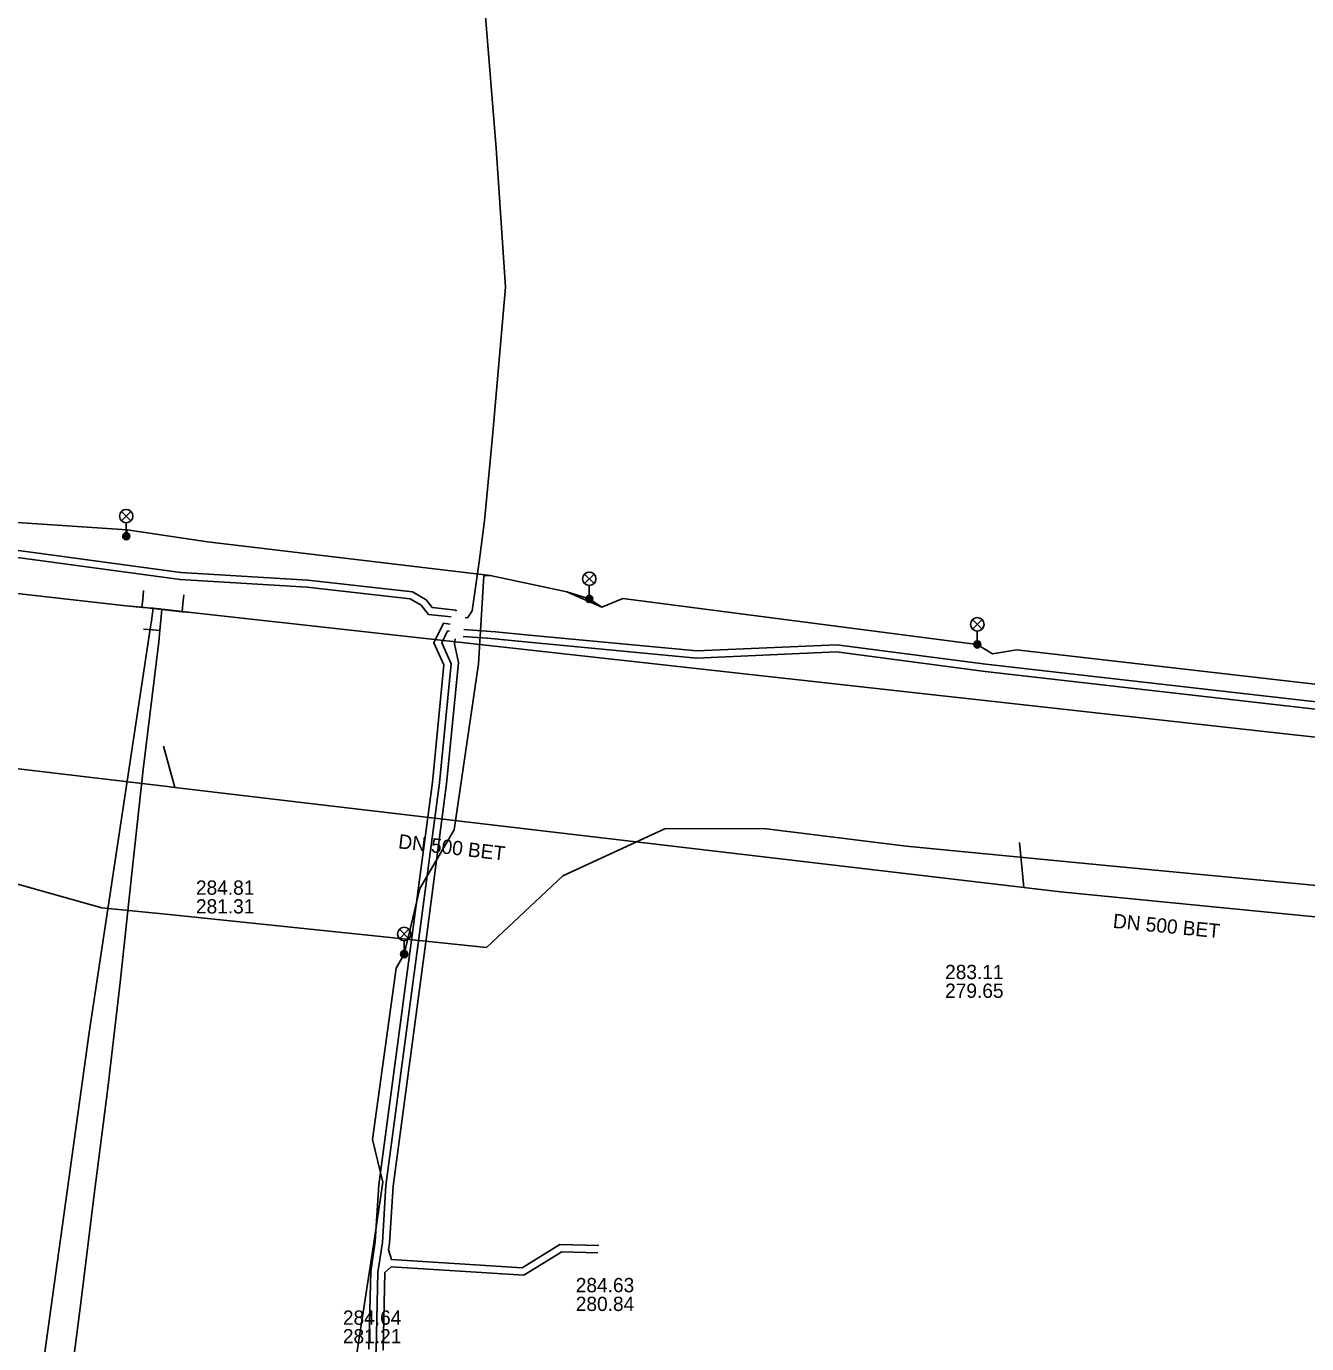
# Model space of a CAD drawing. Extents: x -595540 to -593988, y -1160850 to -1159202.
# Drawn here: x -594220.6 to -594148.9, y -1160478.9 to -1160405.2 of the extents above; entities that cross this region are included whole.
import ezdxf

# ---------------------------------------------------------------- set-up
doc = ezdxf.new("R2010")
doc.units = 0
for name, color, linetype in [('BVK-DESTOVA_popisy', 7, 'Continuous'), ('BVK-DESTOVA_trasa sítě', 7, 'Continuous'), ('BVK-VODOVOD_trasa neprovozované sítě', 7, 'Continuous'), ('BVK-VODOVOD_trasa sítě', 7, 'Continuous'), ('BVK-VODOVOD_trasa zrušené sítě', 7, 'Continuous'), ('CETIN_kabel podzemní', 7, 'Continuous'), ('DESTOVA-NEPROVOZOVANA_popisy', 7, 'Continuous'), ('DESTOVA_trasa neprovozované sítě', 7, 'Continuous'), ('EON-NN_kabel', 7, 'Continuous'), ('SPLASKOVA_popisy neprovozované sítě', 7, 'Continuous'), ('TSB_kabel VO', 7, 'Continuous'), ('TSB_lampy VO', 7, 'Continuous')]:
    doc.layers.add(name, color=color, linetype=linetype)

msp = doc.modelspace()

# ---------------------------------------------------------------- linework, layer by layer
at = {"layer": 'BVK-DESTOVA_popisy'}
for p, q in [((-594211.057, -1160453.94), (-594211.057, -1160453.94)), ((-594169.103, -1160458.665), (-594169.103, -1160458.665))]:
    msp.add_line(p, q, dxfattribs=at)
at = {"layer": 'BVK-DESTOVA_trasa sítě'}
for points in [[(-594244.324, -1160444), (-594212.646, -1160447.758), (-594212.249, -1160447.805), (-594203.869, -1160448.799)], [(-594203.869, -1160448.799), (-594165.305, -1160453.34), (-594164.69, -1160453.413), (-594162.641, -1160453.654)], [(-594162.641, -1160453.654), (-594123.847, -1160457.456), (-594121.411, -1160457.695)]]:
    msp.add_lwpolyline(points, dxfattribs=at)
at = {"layer": 'BVK-VODOVOD_trasa neprovozované sítě'}
for p, q in [((-594212.97, -1160437.84), (-594213.62, -1160437.77)), ((-594212.97, -1160437.84), (-594213.02, -1160438.44)), ((-594212.31, -1160437.92), (-594212.97, -1160437.84))]:
    msp.add_line(p, q, dxfattribs=at)
for points in [[(-594213.62, -1160437.77), (-594214.09, -1160437.72), (-594214.96, -1160437.63)], [(-594211.32, -1160438.02), (-594211.83, -1160437.97), (-594212.31, -1160437.92)], [(-594213.02, -1160438.44), (-594213.08, -1160439.02), (-594213.14, -1160439.66), (-594214.01, -1160446.81), (-594214.67, -1160452.79), (-594215.3, -1160458.72), (-594216, -1160464.65), (-594216.76, -1160470.59), (-594217.49, -1160476.51), (-594218.25, -1160482.46)]]:
    msp.add_lwpolyline(points, dxfattribs=at)
at = {"layer": 'BVK-VODOVOD_trasa sítě'}
for points in [[(-594214.96, -1160437.63), (-594274.08, -1160430.95), (-594306.27, -1160427.23), (-594312.47, -1160426.57), (-594313.618, -1160426.436), (-594314.569, -1160426.328)], [(-594214.09, -1160437.72), (-594214.04, -1160437.29), (-594213.99, -1160436.78)], [(-594211.83, -1160437.97), (-594211.79, -1160437.53), (-594211.74, -1160437.02)], [(-594113.276, -1160448.503), (-594125.48, -1160447.53), (-594211.32, -1160438.02)], [(-594213.08, -1160439.02), (-594213.49, -1160438.98), (-594214, -1160438.94)]]:
    msp.add_lwpolyline(points, dxfattribs=at)
at = {"layer": 'BVK-VODOVOD_trasa zrušené sítě'}
for p, q in [((-594214.027, -1160437.733), (-594214.96, -1160437.63)), ((-594213.459, -1160437.778), (-594214.027, -1160437.733)), ((-594213.459, -1160437.778), (-594213.551, -1160438.474)), ((-594211.32, -1160438.02), (-594213.459, -1160437.778))]:
    msp.add_line(p, q, dxfattribs=at)
msp.add_lwpolyline([(-594213.551, -1160438.474), (-594213.601, -1160438.814), (-594217.04, -1160461.53), (-594223.63, -1160508.9), (-594224.89, -1160519.02), (-594236.25, -1160529.2), (-594237.67, -1160530.464), (-594245.437, -1160537.304), (-594246.41, -1160538.23), (-594259.22, -1160548.81), (-594259.91, -1160549.45), (-594262.55, -1160548.76), (-594263.54, -1160549.66), (-594264.87, -1160550.76), (-594266.65, -1160552.25), (-594269.22, -1160554.37), (-594269.44, -1160560.5), (-594269.912, -1160561.147), (-594270.246, -1160561.625)], dxfattribs=at)
at = {"layer": 'CETIN_kabel podzemní'}
msp.add_lwpolyline([(-594222.52, -1160452.81), (-594216.33, -1160454.54), (-594212.55, -1160454.93), (-594194.78, -1160456.76), (-594190.51, -1160452.76), (-594184.77, -1160450.1), (-594179.1, -1160450.13), (-594171.29, -1160451.1), (-594162.22, -1160451.97), (-594159.7, -1160452.21), (-594139.662, -1160454.119)], dxfattribs=at)
at = {"layer": 'DESTOVA-NEPROVOZOVANA_popisy'}
msp.add_line((-594189.786, -1160477.121), (-594189.786, -1160477.121), dxfattribs=at)
at = {"layer": 'DESTOVA_trasa neprovozované sítě'}
for p, q in [((-594212.873, -1160445.498), (-594212.249, -1160447.805)), ((-594164.93, -1160450.883), (-594164.69, -1160453.413))]:
    msp.add_line(p, q, dxfattribs=at)
at = {"layer": 'EON-NN_kabel'}
for points in [[(-594194.904, -1160403.956), (-594194.236, -1160412.008), (-594193.719, -1160419.801), (-594194.444, -1160428.15), (-594194.905, -1160432.885), (-594195.196, -1160435.178), (-594195.581, -1160437.924), (-594195.824, -1160438.297), (-594195.973, -1160438.308)], [(-594196.463, -1160437.929), (-594196.507, -1160437.886), (-594197.826, -1160437.737), (-594198.169, -1160437.3), (-594198.935, -1160436.856), (-594204.795, -1160436.195), (-594211.899, -1160435.767), (-594220.3, -1160434.636), (-594226.529, -1160433.819), (-594235.45, -1160432.714), (-594247.97, -1160431.519), (-594257.366, -1160430.496), (-594266.358, -1160429.88), (-594275.304, -1160428.268), (-594276.054, -1160427.775), (-594276.181, -1160427.178), (-594276.328, -1160424.743), (-594276.747, -1160421.438), (-594277.287, -1160420.257), (-594279.851, -1160420.114), (-594280.216, -1160420.099), (-594286.508, -1160419.735), (-594287.944, -1160419.605)], [(-594196.773, -1160438.259), (-594198.037, -1160438.116), (-594198.437, -1160437.608), (-594199.063, -1160437.244), (-594204.829, -1160436.593), (-594211.937, -1160436.165), (-594220.352, -1160435.032), (-594226.579, -1160434.215), (-594235.494, -1160433.112), (-594248.01, -1160431.917), (-594257.402, -1160430.894), (-594266.408, -1160430.278), (-594275.456, -1160428.648), (-594276.412, -1160428.019), (-594276.579, -1160427.232), (-594276.726, -1160424.781), (-594277.137, -1160421.548), (-594277.551, -1160420.643), (-594279.84, -1160420.515), (-594280.236, -1160420.499), (-594286.547, -1160420.133), (-594287.98, -1160420.005)], [(-594201.372, -1160479.267), (-594201.269, -1160474.903), (-594201.013, -1160473.236), (-594200.817, -1160470.049), (-594198.927, -1160455.934), (-594197.817, -1160447.512), (-594197.171, -1160440.946), (-594197.739, -1160439.705), (-594197.202, -1160438.614), (-594196.819, -1160438.657)], [(-594169.531, -1160502.245), (-594173.494, -1160503.747), (-594180.8, -1160503.48), (-594187.546, -1160503.094), (-594187.889, -1160502.856), (-594188.148, -1160502.677), (-594187.802, -1160492.632), (-594187.662, -1160491.907), (-594188.169, -1160491.592), (-594194.774, -1160490.25), (-594201.117, -1160488.96), (-594201.746, -1160488.398), (-594201.892, -1160487.481), (-594200.973, -1160479.294), (-594200.87, -1160474.938), (-594200.615, -1160473.279), (-594200.419, -1160470.088), (-594198.53, -1160455.987), (-594197.42, -1160447.558), (-594196.762, -1160440.878), (-594197.296, -1160439.711), (-594196.968, -1160439.042), (-594196.864, -1160439.053)], [(-594188.504, -1160473.456), (-594190.68, -1160473.404), (-594192.792, -1160474.699), (-594200.098, -1160474.239), (-594200.273, -1160473.688), (-594200.217, -1160473.322), (-594200.021, -1160470.127), (-594198.133, -1160456.04), (-594197.023, -1160447.604), (-594196.353, -1160440.81), (-594196.573, -1160439.775), (-594196.543, -1160439.48)], [(-594196.094, -1160439.359), (-594194.77, -1160439.455), (-594194.726, -1160439.457), (-594192.627, -1160439.655), (-594183.025, -1160440.562), (-594175.18, -1160440.223), (-594166.868, -1160441.308), (-594148.038, -1160443.456), (-594139.714, -1160444.195), (-594132.759, -1160445.13), (-594123.636, -1160446.031), (-594123.002, -1160445.543), (-594122.98, -1160445.265), (-594122.605, -1160445.028), (-594122.518, -1160445.033)], [(-594122.014, -1160444.877), (-594122.247, -1160444.453), (-594122.426, -1160444.442), (-594123.364, -1160445.034), (-594123.387, -1160445.334), (-594123.753, -1160445.616), (-594132.713, -1160444.732), (-594139.67, -1160443.797), (-594147.998, -1160443.058), (-594166.82, -1160440.91), (-594175.162, -1160439.821), (-594183.015, -1160440.162), (-594192.589, -1160439.257), (-594194.288, -1160439.097), (-594196.048, -1160438.959)], [(-594188.553, -1160473.855), (-594190.572, -1160473.806), (-594192.69, -1160475.107), (-594200.122, -1160474.639), (-594200.471, -1160474.962), (-594200.574, -1160479.321)]]:
    msp.add_lwpolyline(points, dxfattribs=at)
at = {"layer": 'SPLASKOVA_popisy neprovozované sítě'}
msp.add_line((-594202.827, -1160477.092), (-594202.827, -1160477.092), dxfattribs=at)
at = {"layer": 'TSB_kabel VO'}
for points in [[(-594115.77, -1160439.63), (-594116.44, -1160439.53), (-594117.23, -1160445.35), (-594120.12, -1160445.03), (-594139.21, -1160442.73), (-594140.42, -1160443.22), (-594141.24, -1160442.85), (-594165.1, -1160440.11), (-594166.45, -1160440.32), (-594167.3, -1160439.8), (-594187.15, -1160437.23), (-594188.32, -1160437.71), (-594189.03, -1160437.25), (-594190.28, -1160436.85), (-594194.58, -1160435.94), (-594210.41, -1160434.05), (-594214.9, -1160433.39), (-594214.96, -1160433.74), (-594214.9, -1160433.39), (-594222.48, -1160432.88)], [(-594202.055, -1160479.49), (-594201.123, -1160473.426), (-594200.59, -1160469.909), (-594201.172, -1160467.513), (-594199.842, -1160457.928), (-594199.396, -1160457.139), (-594198.516, -1160453.462), (-594196.596, -1160450.188), (-594195.23, -1160440.889), (-594194.928, -1160435.962), (-594194.58, -1160435.94), (-594190.28, -1160436.85), (-594188.32, -1160437.71), (-594187.15, -1160437.23), (-594167.3, -1160439.8), (-594166.45, -1160440.32), (-594165.1, -1160440.11), (-594141.24, -1160442.85), (-594140.42, -1160443.22), (-594139.21, -1160442.73), (-594120.12, -1160445.03), (-594117.23, -1160445.35), (-594116.44, -1160439.53), (-594115.77, -1160439.63)]]:
    msp.add_lwpolyline(points, dxfattribs=at)
at = {"layer": 'TSB_lampy VO'}
for p, q in [((-594215.225, -1160432.88), (-594214.695, -1160432.35)), ((-594215.225, -1160432.35), (-594214.695, -1160432.88)), ((-594215.225, -1160432.88), (-594214.695, -1160432.35)), ((-594215.225, -1160432.35), (-594214.695, -1160432.88)), ((-594214.96, -1160432.99), (-594214.96, -1160433.74)), ((-594214.96, -1160432.99), (-594214.96, -1160433.74)), ((-594189.295, -1160436.39), (-594188.765, -1160435.86)), ((-594189.295, -1160435.86), (-594188.765, -1160436.39)), ((-594189.295, -1160436.39), (-594188.765, -1160435.86)), ((-594189.295, -1160435.86), (-594188.765, -1160436.39)), ((-594189.03, -1160436.5), (-594189.03, -1160437.25)), ((-594189.03, -1160436.5), (-594189.03, -1160437.25)), ((-594167.565, -1160438.94), (-594167.035, -1160438.41)), ((-594167.565, -1160438.41), (-594167.035, -1160438.94)), ((-594167.565, -1160438.94), (-594167.035, -1160438.41)), ((-594167.565, -1160438.41), (-594167.035, -1160438.94)), ((-594167.3, -1160439.05), (-594167.3, -1160439.8)), ((-594167.3, -1160439.05), (-594167.3, -1160439.8)), ((-594199.661, -1160456.279), (-594199.131, -1160455.749)), ((-594199.661, -1160455.749), (-594199.131, -1160456.279)), ((-594199.661, -1160456.279), (-594199.131, -1160455.749)), ((-594199.661, -1160455.749), (-594199.131, -1160456.279)), ((-594199.396, -1160456.389), (-594199.396, -1160457.139)), ((-594199.396, -1160456.389), (-594199.396, -1160457.139))]:
    msp.add_line(p, q, dxfattribs=at)
for centre, radius in [((-594214.96, -1160432.615), 0.375), ((-594214.96, -1160432.615), 0.375), ((-594214.96, -1160433.74), 0.2), ((-594214.96, -1160433.74), 0.2), ((-594214.96, -1160433.74), 0.145), ((-594214.96, -1160433.74), 0.145), ((-594214.96, -1160433.74), 0.0876), ((-594214.96, -1160433.74), 0.0876), ((-594189.03, -1160436.125), 0.375), ((-594189.03, -1160436.125), 0.375), ((-594189.03, -1160437.25), 0.2), ((-594189.03, -1160437.25), 0.2), ((-594189.03, -1160437.25), 0.145), ((-594189.03, -1160437.25), 0.145), ((-594189.03, -1160437.25), 0.0876), ((-594189.03, -1160437.25), 0.0876), ((-594167.3, -1160438.675), 0.375), ((-594167.3, -1160438.675), 0.375), ((-594167.3, -1160439.8), 0.2), ((-594167.3, -1160439.8), 0.2), ((-594167.3, -1160439.8), 0.145), ((-594167.3, -1160439.8), 0.145), ((-594167.3, -1160439.8), 0.0876), ((-594167.3, -1160439.8), 0.0876), ((-594199.396, -1160456.014), 0.375), ((-594199.396, -1160456.014), 0.375), ((-594199.396, -1160457.139), 0.2), ((-594199.396, -1160457.139), 0.2), ((-594199.396, -1160457.139), 0.145), ((-594199.396, -1160457.139), 0.145), ((-594199.396, -1160457.139), 0.0876), ((-594199.396, -1160457.139), 0.0876)]:
    msp.add_circle(centre, radius, dxfattribs=at)

# ---------------------------------------------------------------- texts
at = {"layer": 'BVK-DESTOVA_popisy'}
for rotation, p in [(353.28578, (-594199.758, -1160451.21)), (354.3744, (-594159.731, -1160455.666))]:
    msp.add_text('DN 500 BET', height=0.8, rotation=rotation, dxfattribs=at).set_placement(p)
for s, p in [('284.81', (-594211.057, -1160453.815)), ('281.31', (-594211.057, -1160454.865)), ('283.11', (-594169.103, -1160458.54)), ('279.65', (-594169.103, -1160459.59))]:
    msp.add_text(s, height=0.8, dxfattribs=at).set_placement(p)
at = {"layer": 'DESTOVA-NEPROVOZOVANA_popisy'}
for s, p in [('284.63', (-594189.786, -1160476.071)), ('280.84', (-594189.786, -1160477.121))]:
    msp.add_text(s, height=0.8, dxfattribs=at).set_placement(p)
at = {"layer": 'SPLASKOVA_popisy neprovozované sítě'}
for s, p in [('284.64', (-594202.827, -1160477.892)), ('281.21', (-594202.827, -1160478.932))]:
    msp.add_text(s, height=0.8, dxfattribs=at).set_placement(p)

doc.saveas('drawing.dxf')
